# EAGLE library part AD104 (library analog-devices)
ANALOG DEVICES
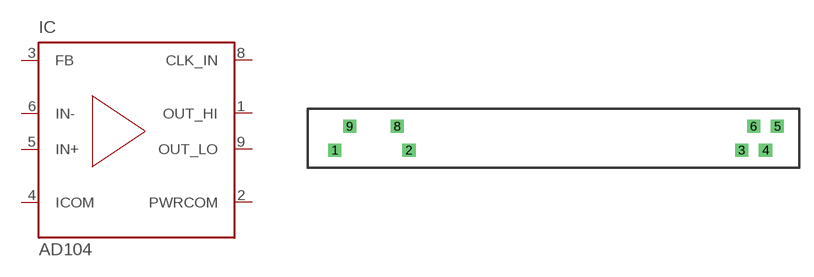
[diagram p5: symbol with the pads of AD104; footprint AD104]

Designator prefix IC

## AD104 (MPN: AD1047; OC_FARNELL: unknown; OC_NEWARK: 27R0347)  [AD104]
1  OUT_HI  out
2  PWRCOM  out
3  FB  in
4  ICOM  pwr
5  IN+  in
6  IN-  in
8  CLK_IN  out
9  OUT_LO  out

## Footprint AD104 (pad centres in mm)
8 lead Package
drill 0.813 pad 1.397 square: 1 -23.368,-1.27; 2 -15.443,-1.27; 3 20.117,-1.27; 4 22.657,-1.27; 5 23.927,1.27; 6 21.387,1.27; 8 -16.713,1.27; 9 -21.793,1.27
